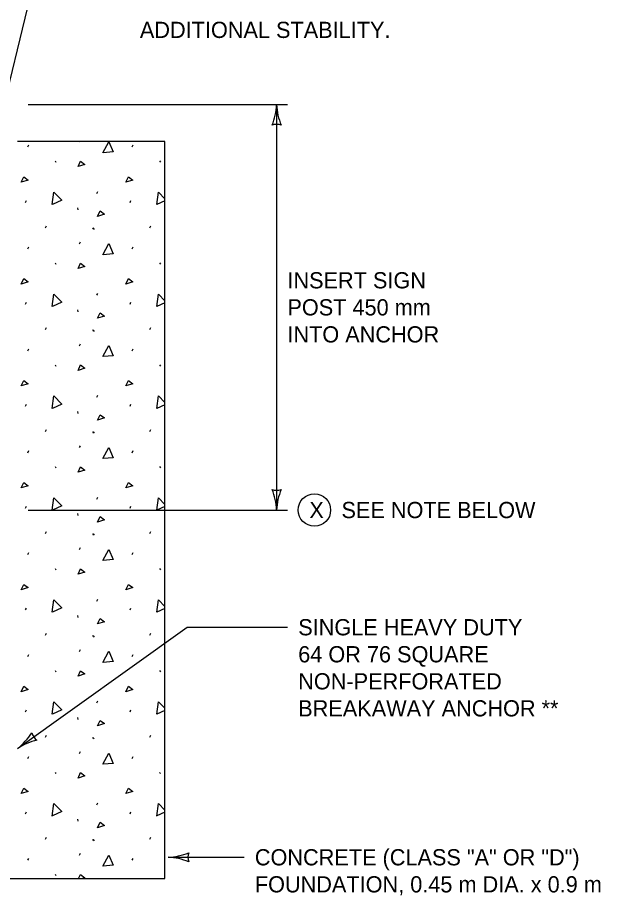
# Model space of a CAD drawing. Extents: x 49940 to 50043, y 49986 to 50011.
# Drawn here: x 50039.957 to 50042.114, y 49990.606 to 49993.853 of the extents above; entities that cross this region are included whole.
import ezdxf

# ---------------------------------------------------------------- set-up
doc = ezdxf.new("R2010")
doc.units = 0
for name, color, linetype in [('Level 1', 7, 'Continuous'), ('Level 2', 7, 'Continuous'), ('Level 3', 7, 'Continuous')]:
    doc.layers.add(name, color=color, linetype=linetype)

msp = doc.modelspace()

# ---------------------------------------------------------------- linework, layer by layer
at = {"layer": 'Level 1'}
for p, q in [((50040.5018, 49993.3944), (50039.9566, 49993.3944)), ((50040.1861, 49993.3929), (50040.1868, 49993.3944)), ((50040.5018, 49990.6682), (50040.5018, 49993.3944)), ((50039.9948, 49993.3744), (50039.9981, 49993.3816)), ((50040.3814, 49993.3744), (50040.3846, 49993.3816)), ((50040.0958, 49993.3227), (50040.0989, 49993.3179)), ((50040.4823, 49993.3227), (50040.4854, 49993.3179)), ((50040.2507, 49993.2026), (50040.2539, 49993.2097)), ((50039.9868, 49993.1693), (50039.99, 49993.1767)), ((50040.3734, 49993.1693), (50040.3766, 49993.1767)), ((50040.1787, 49993.1491), (50040.1794, 49993.1419)), ((50040.0602, 49993.0757), (50040.0635, 49993.083)), ((50040.2338, 49993.0757), (50040.2369, 49993.071)), ((50040.2369, 49993.0739), (50040.2402, 49993.069)), ((50040.4469, 49993.0757), (50040.4499, 49993.083)), ((50039.9948, 49992.9974), (50039.9981, 49993.0046)), ((50040.1861, 49993.016), (50040.1894, 49993.0232)), ((50040.3814, 49992.9974), (50040.3846, 49993.0046)), ((50040.0958, 49992.9458), (50040.0989, 49992.9409)), ((50040.4823, 49992.9458), (50040.4854, 49992.9409)), ((50040.2507, 49992.8255), (50040.2539, 49992.8327)), ((50039.9868, 49992.7924), (50039.99, 49992.7996)), ((50040.3734, 49992.7924), (50040.3766, 49992.7996)), ((50040.1787, 49992.7721), (50040.1794, 49992.7649)), ((50040.0602, 49992.6988), (50040.0635, 49992.706)), ((50040.4469, 49992.6988), (50040.4499, 49992.706)), ((50040.2338, 49992.6988), (50040.2369, 49992.694)), ((50040.2369, 49992.697), (50040.2402, 49992.6922)), ((50040.1861, 49992.639), (50040.1894, 49992.6463)), ((50039.9948, 49992.6205), (50039.9981, 49992.6277)), ((50040.3814, 49992.6205), (50040.3846, 49992.6277)), ((50040.0958, 49992.5689), (50040.0989, 49992.564)), ((50040.4823, 49992.5689), (50040.4854, 49992.564)), ((50040.2507, 49992.4485), (50040.2539, 49992.4558)), ((50039.9868, 49992.4155), (50039.99, 49992.4227)), ((50040.3734, 49992.4155), (50040.3766, 49992.4227)), ((50040.1787, 49992.3952), (50040.1794, 49992.388)), ((50040.0602, 49992.3218), (50040.0635, 49992.3291)), ((50040.2338, 49992.3218), (50040.2369, 49992.317)), ((50040.2369, 49992.32), (50040.2402, 49992.3152)), ((50040.4469, 49992.3218), (50040.4499, 49992.3291)), ((50039.9948, 49992.2434), (50039.9981, 49992.2509)), ((50040.1861, 49992.262), (50040.1894, 49992.2693)), ((50040.3814, 49992.2434), (50040.3846, 49992.2509)), ((50040.0958, 49992.1918), (50040.0989, 49992.187)), ((50040.4823, 49992.1918), (50040.4854, 49992.187)), ((50040.2507, 49992.0716), (50040.2539, 49992.0789)), ((50039.9868, 49992.0385), (50039.99, 49992.0458)), ((50040.3734, 49992.0385), (50040.3766, 49992.0458)), ((50040.1787, 49992.0182), (50040.1794, 49992.011)), ((50040.0602, 49991.9449), (50040.0635, 49991.9522)), ((50040.2338, 49991.9449), (50040.2369, 49991.94)), ((50040.2369, 49991.943), (50040.2402, 49991.9381)), ((50040.4469, 49991.9449), (50040.4499, 49991.9522)), ((50040.1861, 49991.8851), (50040.1894, 49991.8924)), ((50039.9948, 49991.8665), (50039.9981, 49991.8737)), ((50040.3814, 49991.8665), (50040.3846, 49991.8737)), ((50040.0958, 49991.8148), (50040.0989, 49991.8101)), ((50040.4823, 49991.8148), (50040.4854, 49991.8101)), ((50040.2507, 49991.6946), (50040.2539, 49991.7018)), ((50039.9868, 49991.6616), (50039.99, 49991.6687)), ((50040.3734, 49991.6616), (50040.3766, 49991.6687)), ((50040.1787, 49991.6412), (50040.1794, 49991.6338)), ((50040.0602, 49991.5678), (50040.0635, 49991.5752)), ((50040.2338, 49991.5678), (50040.2369, 49991.563)), ((50040.2369, 49991.566), (50040.2402, 49991.5612)), ((50040.4469, 49991.5678), (50040.4499, 49991.5752)), ((50040.1861, 49991.5081), (50040.1894, 49991.5153)), ((50039.9948, 49991.4896), (50039.9981, 49991.4968)), ((50040.3814, 49991.4896), (50040.3846, 49991.4968)), ((50040.0958, 49991.4378), (50040.0989, 49991.4331)), ((50040.4823, 49991.4378), (50040.4854, 49991.4331)), ((50040.2507, 49991.3177), (50040.2539, 49991.3249)), ((50039.9868, 49991.2846), (50039.99, 49991.2918)), ((50040.3734, 49991.2846), (50040.3766, 49991.2918)), ((50040.1787, 49991.2643), (50040.1794, 49991.2569)), ((50040.0602, 49991.191), (50040.0635, 49991.1982)), ((50040.2338, 49991.191), (50040.2369, 49991.1861)), ((50040.2369, 49991.1891), (50040.2402, 49991.1844)), ((50040.4469, 49991.191), (50040.4499, 49991.1982)), ((50039.9948, 49991.1126), (50039.9981, 49991.1198)), ((50040.1861, 49991.1311), (50040.1894, 49991.1384)), ((50040.3814, 49991.1126), (50040.3846, 49991.1198)), ((50040.0958, 49991.0609), (50040.0989, 49991.0561)), ((50040.4823, 49991.0609), (50040.4854, 49991.0561)), ((50040.2507, 49990.9407), (50040.2539, 49990.948)), ((50039.9868, 49990.9076), (50039.99, 49990.9148)), ((50040.1787, 49990.8873), (50040.1794, 49990.8801)), ((50040.3734, 49990.9076), (50040.3766, 49990.9148)), ((50040.0602, 49990.814), (50040.0635, 49990.8212)), ((50040.4469, 49990.814), (50040.4499, 49990.8212)), ((50040.2338, 49990.814), (50040.2369, 49990.8091)), ((50040.2369, 49990.8121), (50040.2402, 49990.8073)), ((50040.1861, 49990.7542), (50040.1894, 49990.7614)), ((50039.9948, 49990.7356), (50039.9981, 49990.7428)), ((50040.3814, 49990.7356), (50040.3846, 49990.7428)), ((50038.9568, 49990.6682), (50040.5018, 49990.6682)), ((50040.0958, 49990.6839), (50040.0989, 49990.679))]:
    msp.add_line(p, q, dxfattribs=at)
for points in [[(50040.2726, 49993.3527), (50040.2942, 49993.3938), (50040.3112, 49993.3559), (50040.2733, 49993.3527)], [(50040.1806, 49993.3016), (50040.1901, 49993.3219), (50040.2063, 49993.3098), (50040.1806, 49993.3016)], [(50039.9708, 49993.244), (50039.9805, 49993.2642), (50039.9966, 49993.2521), (50039.9708, 49993.244)], [(50040.3573, 49993.244), (50040.367, 49993.2642), (50040.3832, 49993.2521), (50040.3573, 49993.244)], [(50040.0851, 49993.1611), (50040.0914, 49993.2072), (50040.1203, 49993.1773), (50040.0857, 49993.1613)], [(50040.4716, 49993.1611), (50040.4778, 49993.2072), (50040.5018, 49993.1827)], [(50040.5018, 49993.1749), (50040.4723, 49993.1613)], [(50040.2523, 49993.1177), (50040.262, 49993.1379), (50040.2782, 49993.1258), (50040.2523, 49993.1177)], [(50040.2726, 49992.9757), (50040.2942, 49993.0168), (50040.3112, 49992.9789), (50040.2733, 49992.9757)], [(50040.1806, 49992.9248), (50040.1901, 49992.945), (50040.2063, 49992.9327), (50040.1806, 49992.9248)], [(50039.9708, 49992.8671), (50039.9805, 49992.8874), (50039.9966, 49992.8751), (50039.9708, 49992.8671)], [(50040.3573, 49992.8671), (50040.367, 49992.8874), (50040.3832, 49992.8751), (50040.3573, 49992.8671)], [(50040.0851, 49992.784), (50040.0914, 49992.8301), (50040.1203, 49992.8004), (50040.0857, 49992.7843)], [(50040.4716, 49992.784), (50040.4778, 49992.8301), (50040.5018, 49992.8056)], [(50040.5018, 49992.798), (50040.4723, 49992.7843)], [(50040.2523, 49992.7407), (50040.262, 49992.761), (50040.2782, 49992.749), (50040.2523, 49992.7407)], [(50040.2726, 49992.5987), (50040.2942, 49992.6398), (50040.3112, 49992.6019), (50040.2733, 49992.5987)], [(50040.1806, 49992.5478), (50040.1901, 49992.568), (50040.2063, 49992.5558), (50040.1806, 49992.5478)], [(50039.9708, 49992.4902), (50039.9805, 49992.5103), (50039.9966, 49992.4982), (50039.9708, 49992.4902)], [(50040.3573, 49992.4902), (50040.367, 49992.5103), (50040.3832, 49992.4982), (50040.3573, 49992.4902)], [(50040.0851, 49992.4071), (50040.0914, 49992.4533), (50040.1203, 49992.4233), (50040.0857, 49992.4074)], [(50040.4716, 49992.4071), (50040.4778, 49992.4533), (50040.5018, 49992.4287)], [(50040.5018, 49992.421), (50040.4723, 49992.4074)], [(50040.2523, 49992.3638), (50040.262, 49992.384), (50040.2782, 49992.3718), (50040.2523, 49992.3638)], [(50040.2726, 49992.2217), (50040.2942, 49992.2628), (50040.3112, 49992.2248), (50040.2733, 49992.2217)], [(50040.1806, 49992.1708), (50040.1901, 49992.191), (50040.2063, 49992.179), (50040.1806, 49992.1708)], [(50039.9708, 49992.1131), (50039.9805, 49992.1334), (50039.9966, 49992.1213), (50039.9708, 49992.1131)], [(50040.3573, 49992.1131), (50040.367, 49992.1334), (50040.3832, 49992.1213), (50040.3573, 49992.1131)], [(50040.0851, 49992.0302), (50040.0914, 49992.0764), (50040.1203, 49992.0463), (50040.0857, 49992.0304)], [(50040.4716, 49992.0302), (50040.4778, 49992.0764), (50040.5018, 49992.0517)], [(50040.5018, 49992.044), (50040.4723, 49992.0304)], [(50040.2523, 49991.9867), (50040.262, 49992.0071), (50040.2782, 49991.9948), (50040.2523, 49991.9867)], [(50040.2726, 49991.8446), (50040.2942, 49991.8858), (50040.3112, 49991.848), (50040.2733, 49991.8446)], [(50040.1806, 49991.7939), (50040.1901, 49991.8139), (50040.2063, 49991.802), (50040.1806, 49991.7939)], [(50039.9708, 49991.7362), (50039.9805, 49991.7563), (50039.9966, 49991.7442), (50039.9708, 49991.7362)], [(50040.3573, 49991.7362), (50040.367, 49991.7563), (50040.3832, 49991.7442), (50040.3573, 49991.7362)], [(50040.0851, 49991.6531), (50040.0914, 49991.6993), (50040.1203, 49991.6694), (50040.0857, 49991.6534)], [(50040.4716, 49991.6531), (50040.4778, 49991.6993), (50040.5018, 49991.6748)], [(50040.5018, 49991.6671), (50040.4723, 49991.6534)], [(50040.2523, 49991.6099), (50040.262, 49991.6301), (50040.2782, 49991.6179), (50040.2523, 49991.6099)], [(50040.2726, 49991.4678), (50040.2942, 49991.5088), (50040.3112, 49991.471), (50040.2733, 49991.4678)], [(50040.1806, 49991.417), (50040.1901, 49991.437), (50040.2063, 49991.425), (50040.1806, 49991.417)], [(50039.9708, 49991.3592), (50039.9805, 49991.3794), (50039.9966, 49991.3674), (50039.9708, 49991.3592)], [(50040.3573, 49991.3592), (50040.367, 49991.3794), (50040.3832, 49991.3674), (50040.3573, 49991.3592)], [(50040.0851, 49991.2761), (50040.0914, 49991.3223), (50040.1203, 49991.2924), (50040.0857, 49991.2766)], [(50040.4716, 49991.2761), (50040.4778, 49991.3223), (50040.5018, 49991.2978)], [(50040.5018, 49991.29), (50040.4723, 49991.2766)], [(50040.2523, 49991.233), (50040.262, 49991.253), (50040.2782, 49991.241), (50040.2523, 49991.233)], [(50040.2726, 49991.0907), (50040.2942, 49991.1319), (50040.3112, 49991.0939), (50040.2733, 49991.0907)], [(50040.1806, 49991.0398), (50040.1901, 49991.06), (50040.2063, 49991.048), (50040.1806, 49991.0398)], [(50039.9708, 49990.9822), (50039.9805, 49991.0024), (50039.9966, 49990.9904), (50039.9708, 49990.9822)], [(50040.3573, 49990.9822), (50040.367, 49991.0024), (50040.3832, 49990.9904), (50040.3573, 49990.9822)], [(50040.0851, 49990.8992), (50040.0914, 49990.9453), (50040.1203, 49990.9155), (50040.0857, 49990.8995)], [(50040.4716, 49990.8992), (50040.4778, 49990.9453), (50040.5018, 49990.9208)], [(50040.5018, 49990.913), (50040.4723, 49990.8995)], [(50040.2523, 49990.856), (50040.262, 49990.876), (50040.2782, 49990.864), (50040.2523, 49990.856)], [(50040.2726, 49990.7139), (50040.2942, 49990.755), (50040.3112, 49990.717), (50040.2733, 49990.7139)], [(50040.1829, 49990.6682), (50040.1901, 49990.6832), (50040.2063, 49990.6711), (50040.1972, 49990.6682)]]:
    msp.add_lwpolyline(points, dxfattribs=at)
at = {"layer": 'Level 2'}
msp.add_circle((50041.0553, 49992.0313), 0.06, dxfattribs=at)
at = {"layer": 'Level 3'}
for p, q in [((50039.8897, 49993.4639), (50040.1695, 49994.6075)), ((50039.9966, 49993.5309), (50040.9553, 49993.5309)), ((50040.9153, 49993.5309), (50040.9153, 49992.0313)), ((50039.9966, 49992.0313), (50040.9553, 49992.0313)), ((50039.9571, 49991.1491), (50040.5843, 49991.5977)), ((50040.5843, 49991.5977), (50040.9553, 49991.5977)), ((50040.514, 49990.7467), (50040.7948, 49990.7467))]:
    msp.add_line(p, q, dxfattribs=at)
for centre, radius, start, end in [((50040.6932, 49993.5401), 0.2223, 337.456, 357.6395), ((50041.148, 49993.5424), 0.233, 182.8273, 202.0772), ((50040.9153, 49993.4027), 0.0548, 72.1388, 107.8612), ((50040.9153, 49992.1595), 0.0548, 252.1388, 287.8612), ((50040.6826, 49992.0198), 0.233, 2.8273, 22.0772), ((50041.1375, 49992.0221), 0.2223, 157.456, 177.6395), ((50039.8124, 49991.3317), 0.233, 308.404, 327.6539), ((50040.0789, 49990.9631), 0.2223, 103.0327, 123.2162), ((50040.0614, 49991.2237), 0.0548, 197.7155, 233.4379), ((50040.5025, 49990.9794), 0.233, 272.8273, 292.0772), ((50040.6422, 49990.7467), 0.0548, 162.1388, 197.8612), ((50040.5049, 49990.5246), 0.2223, 67.456, 87.6395)]:
    msp.add_arc(centre, radius, start, end, dxfattribs=at)

# ---------------------------------------------------------------- texts
at = {"layer": 'Level 2'}
for s, p in [('ADDITIONAL STABILITY.', (50040.4094, 49993.7775)), ('INSERT SIGN', (50040.9553, 49992.8511)), ('POST 450 mm', (50040.9553, 49992.7511)), ('INTO ANCHOR', (50040.9553, 49992.6511)), ('X', (50041.0365, 49992.0013)), ('SEE NOTE BELOW', (50041.1553, 49992.0013)), ('SINGLE HEAVY DUTY', (50040.9953, 49991.5677)), ('64 OR 76 SQUARE', (50040.9953, 49991.4677)), ('NON-PERFORATED', (50040.9953, 49991.3677)), ('BREAKAWAY ANCHOR **', (50040.9953, 49991.2677)), ('CONCRETE (CLASS "A" OR "D")', (50040.8348, 49990.7167)), ('FOUNDATION, 0.45 m DIA. x 0.9 m', (50040.8348, 49990.6167))]:
    msp.add_text(s, height=0.06, dxfattribs=at).set_placement(p)

doc.saveas('drawing.dxf')
